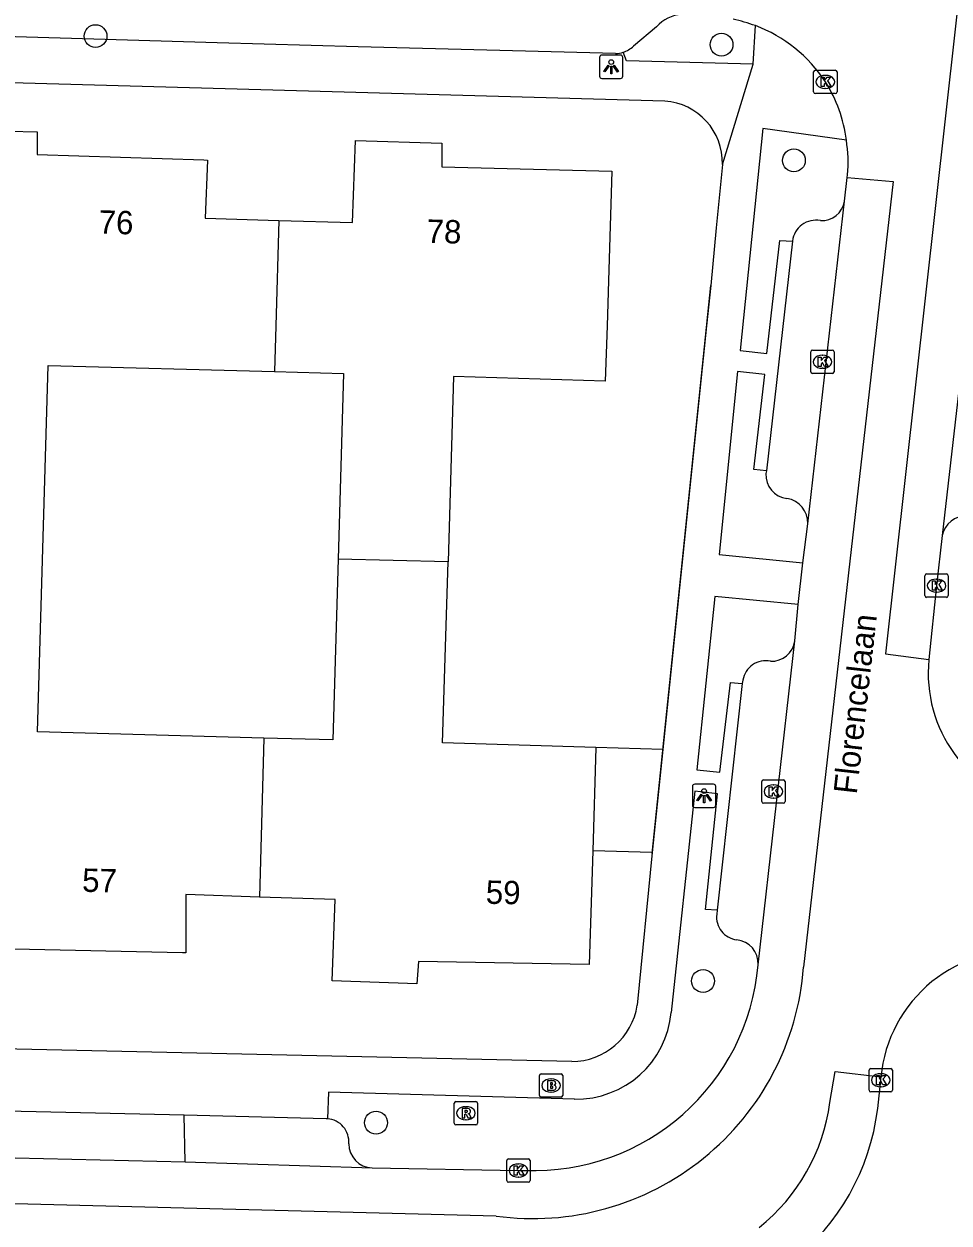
# Model space of a CAD drawing. Extents: x 162082 to 163393, y 388091 to 388632.
# Drawn here: x 162691.6 to 162731.2, y 388461.6 to 388512.9 of the extents above; entities that cross this region are included whole.
import ezdxf

# ---------------------------------------------------------------- set-up
doc = ezdxf.new("R2010")
doc.units = 0
for name, color, linetype in [('IMGEO_Boom', 7, 'Continuous'), ('IMGEO_Brandkraan', 7, 'Continuous'), ('IMGEO_Kolk', 7, 'Continuous'), ('IMGEO_Lichtpunt', 7, 'Continuous'), ('IMGEO_Muur', 7, 'Continuous'), ('IMGEO_Openbare_ruimte_label', 7, 'Continuous'), ('IMGEO_Pand', 7, 'Continuous'), ('IMGEO_Pand_nummerreeks', 7, 'Continuous'), ('IMGEO_Parkeervlak_open', 7, 'Continuous'), ('IMGEO_Rijbaan_lokaal_gesloten', 7, 'Continuous'), ('IMGEO_Rijbaan_lokaal_open', 7, 'Continuous'), ('IMGEO_Rioolput', 7, 'Continuous'), ('IMGEO_Voetpad_open', 7, 'Continuous')]:
    doc.layers.add(name, color=color, linetype=linetype)

msp = doc.modelspace()

# ---------------------------------------------------------------- linework, layer by layer
at = {"layer": 'IMGEO_Boom'}
for centre in [(162694.656, 388512.408), (162721.466, 388512.043), (162724.565, 388507.085), (162720.675, 388471.937), (162706.669, 388465.867)]:
    msp.add_circle(centre, 0.489, dxfattribs=at)
at = {"layer": 'IMGEO_Brandkraan'}
for p, q in [((162713.665, 388467.034), (162713.665, 388467.886)), ((162713.74, 388467.96), (162714.592, 388467.96)), ((162714.153, 388467.74), (162714.178, 388467.74)), ((162714.666, 388467.886), (162714.666, 388467.034)), ((162714.176, 388467.18), (162714.151, 388467.18)), ((162714.592, 388466.96), (162713.74, 388466.96))]:
    msp.add_line(p, q, dxfattribs=at)
for points in [[(162713.665, 388467.034), (162713.665, 388467.886)], [(162713.74, 388467.96), (162714.592, 388467.96)], [(162714.013, 388467.66), (162714.013, 388467.26), (162714.226, 388467.26)], [(162714.244, 388467.66), (162714.013, 388467.66)], [(162714.192, 388467.579), (162714.138, 388467.579), (162714.138, 388467.503)], [(162714.138, 388467.503), (162714.191, 388467.503)], [(162714.666, 388467.886), (162714.666, 388467.034)], [(162714.2, 388467.427), (162714.138, 388467.427), (162714.138, 388467.346)], [(162714.138, 388467.346), (162714.2, 388467.346)], [(162714.592, 388466.96), (162713.74, 388466.96)]]:
    msp.add_lwpolyline(points, dxfattribs=at)
for centre, radius, start, end in [((162713.742, 388467.884), 0.0765, 91.552, 178.448), ((162713.742, 388467.884), 0.0765, 91.552, 178.448), ((162714.193, 388467.541), 0.0379, 267.8285, 90.9355), ((162714.248, 388467.515), 0.145, 59.4692, 91.5367), ((162714.273, 388467.562), 0.0922, 285.5137, 58.1501), ((162714.59, 388467.884), 0.0765, 1.552, 88.448), ((162714.59, 388467.884), 0.0765, 1.552, 88.448), ((162713.742, 388467.036), 0.0765, 181.552, 268.448), ((162713.742, 388467.036), 0.0765, 181.552, 268.448), ((162714.201, 388467.386), 0.0404, 269.8759, 90.5077), ((162714.232, 388467.511), 0.251, 268.6676, 293.5347), ((162714.278, 388467.37), 0.105, 301.3115, 78.989), ((162714.59, 388467.036), 0.0765, 271.552, 358.448), ((162714.59, 388467.036), 0.0765, 271.552, 358.448)]:
    msp.add_arc(centre, radius, start, end, dxfattribs=at)
for centre, major_axis, ratio, start_param, end_param in [((162714.152, 388467.46), (-0.387, 0.002), 0.722429, 4.712389, 7.853982), ((162714.177, 388467.46), (-0.39, 0.002), 0.717154, 1.570796, 4.712389)]:
    msp.add_ellipse(centre, major_axis=major_axis, ratio=ratio, start_param=start_param, end_param=end_param, dxfattribs=at)
at = {"layer": 'IMGEO_Kolk'}
for p, q in [((162725.411, 388510.021), (162725.411, 388510.873)), ((162725.486, 388510.947), (162726.338, 388510.947)), ((162725.899, 388510.727), (162725.924, 388510.727)), ((162726.412, 388510.873), (162726.412, 388510.021)), ((162725.922, 388510.167), (162725.897, 388510.167)), ((162726.338, 388509.947), (162725.486, 388509.947)), ((162725.288, 388498.035), (162725.288, 388498.887)), ((162725.363, 388498.961), (162726.215, 388498.961)), ((162726.289, 388498.887), (162726.289, 388498.035)), ((162725.776, 388498.741), (162725.801, 388498.741)), ((162726.215, 388497.961), (162725.363, 388497.961)), ((162725.799, 388498.181), (162725.774, 388498.181)), ((162730.174, 388488.444), (162730.174, 388489.296)), ((162730.249, 388489.37), (162731.101, 388489.37)), ((162730.662, 388489.15), (162730.687, 388489.15)), ((162731.175, 388489.296), (162731.175, 388488.444)), ((162730.685, 388488.59), (162730.66, 388488.59)), ((162731.101, 388488.37), (162730.249, 388488.37)), ((162723.188, 388479.626), (162723.188, 388480.478)), ((162723.263, 388480.552), (162724.115, 388480.552)), ((162723.676, 388480.332), (162723.701, 388480.332)), ((162724.189, 388480.478), (162724.189, 388479.626)), ((162724.115, 388479.552), (162723.263, 388479.552)), ((162723.699, 388479.772), (162723.674, 388479.772)), ((162727.785, 388467.26), (162727.785, 388468.112)), ((162727.86, 388468.186), (162728.712, 388468.186)), ((162728.786, 388468.112), (162728.786, 388467.26)), ((162728.273, 388467.966), (162728.298, 388467.966)), ((162728.712, 388467.186), (162727.86, 388467.186)), ((162728.296, 388467.406), (162728.271, 388467.406)), ((162712.267, 388463.392), (162712.267, 388464.244)), ((162712.342, 388464.318), (162713.194, 388464.318)), ((162712.755, 388464.098), (162712.78, 388464.098)), ((162713.268, 388464.244), (162713.268, 388463.392)), ((162712.778, 388463.538), (162712.753, 388463.538)), ((162713.194, 388463.318), (162712.342, 388463.318))]:
    msp.add_line(p, q, dxfattribs=at)
for points in [[(162725.411, 388510.021), (162725.411, 388510.873)], [(162725.486, 388510.947), (162726.338, 388510.947)], [(162725.732, 388510.647), (162725.855, 388510.647), (162725.855, 388510.496), (162725.985, 388510.647), (162726.149, 388510.647), (162726.003, 388510.496), (162726.156, 388510.247), (162726.004, 388510.247), (162725.919, 388510.411), (162725.855, 388510.344), (162725.855, 388510.247), (162725.732, 388510.247), (162725.732, 388510.647)], [(162726.412, 388510.873), (162726.412, 388510.021)], [(162726.338, 388509.947), (162725.486, 388509.947)], [(162725.288, 388498.035), (162725.288, 388498.887)], [(162725.363, 388498.961), (162726.215, 388498.961)], [(162726.289, 388498.887), (162726.289, 388498.035)], [(162725.609, 388498.661), (162725.732, 388498.661), (162725.732, 388498.51), (162725.862, 388498.661), (162726.026, 388498.661), (162725.88, 388498.51), (162726.033, 388498.261), (162725.881, 388498.261), (162725.796, 388498.425), (162725.732, 388498.358), (162725.732, 388498.261), (162725.609, 388498.261), (162725.609, 388498.661)], [(162726.215, 388497.961), (162725.363, 388497.961)], [(162730.174, 388488.444), (162730.174, 388489.296)], [(162730.249, 388489.37), (162731.101, 388489.37)], [(162730.495, 388489.07), (162730.618, 388489.07), (162730.618, 388488.919), (162730.748, 388489.07), (162730.912, 388489.07), (162730.766, 388488.919), (162730.919, 388488.67), (162730.767, 388488.67), (162730.682, 388488.834), (162730.618, 388488.767), (162730.618, 388488.67), (162730.495, 388488.67), (162730.495, 388489.07)], [(162731.175, 388489.296), (162731.175, 388488.444)], [(162731.101, 388488.37), (162730.249, 388488.37)], [(162723.188, 388479.626), (162723.188, 388480.478)], [(162723.263, 388480.552), (162724.115, 388480.552)], [(162724.189, 388480.478), (162724.189, 388479.626)], [(162723.509, 388480.252), (162723.632, 388480.252), (162723.632, 388480.101), (162723.762, 388480.252), (162723.926, 388480.252), (162723.78, 388480.101), (162723.933, 388479.852), (162723.781, 388479.852), (162723.696, 388480.016), (162723.632, 388479.949), (162723.632, 388479.852), (162723.509, 388479.852), (162723.509, 388480.252)], [(162724.115, 388479.552), (162723.263, 388479.552)], [(162727.785, 388467.26), (162727.785, 388468.112)], [(162727.86, 388468.186), (162728.712, 388468.186)], [(162728.786, 388468.112), (162728.786, 388467.26)], [(162728.106, 388467.886), (162728.229, 388467.886), (162728.229, 388467.735), (162728.359, 388467.886), (162728.523, 388467.886), (162728.377, 388467.735), (162728.53, 388467.486), (162728.378, 388467.486), (162728.293, 388467.65), (162728.229, 388467.583), (162728.229, 388467.486), (162728.106, 388467.486), (162728.106, 388467.886)], [(162728.712, 388467.186), (162727.86, 388467.186)], [(162712.267, 388463.392), (162712.267, 388464.244)], [(162712.342, 388464.318), (162713.194, 388464.318)], [(162712.588, 388464.018), (162712.711, 388464.018), (162712.711, 388463.867), (162712.841, 388464.018), (162713.005, 388464.018), (162712.859, 388463.867), (162713.012, 388463.618), (162712.86, 388463.618), (162712.775, 388463.782), (162712.711, 388463.715), (162712.711, 388463.618), (162712.588, 388463.618), (162712.588, 388464.018)], [(162713.268, 388464.244), (162713.268, 388463.392)], [(162713.194, 388463.318), (162712.342, 388463.318)]]:
    msp.add_lwpolyline(points, dxfattribs=at)
for centre, start, end in [((162725.488, 388510.871), 91.552, 178.448), ((162725.488, 388510.871), 91.552, 178.448), ((162726.336, 388510.871), 1.552, 88.448), ((162726.336, 388510.871), 1.552, 88.448), ((162725.488, 388510.023), 181.552, 268.448), ((162725.488, 388510.023), 181.552, 268.448), ((162726.336, 388510.023), 271.552, 358.448), ((162726.336, 388510.023), 271.552, 358.448), ((162725.365, 388498.885), 91.552, 178.448), ((162725.365, 388498.885), 91.552, 178.448), ((162726.213, 388498.885), 1.552, 88.448), ((162726.213, 388498.885), 1.552, 88.448), ((162725.365, 388498.037), 181.552, 268.448), ((162725.365, 388498.037), 181.552, 268.448), ((162726.213, 388498.037), 271.552, 358.448), ((162726.213, 388498.037), 271.552, 358.448), ((162730.251, 388489.294), 91.552, 178.448), ((162730.251, 388489.294), 91.552, 178.448), ((162731.099, 388489.294), 1.552, 88.448), ((162731.099, 388489.294), 1.552, 88.448), ((162730.251, 388488.446), 181.552, 268.448), ((162730.251, 388488.446), 181.552, 268.448), ((162731.099, 388488.446), 271.552, 358.448), ((162731.099, 388488.446), 271.552, 358.448), ((162723.265, 388480.476), 91.552, 178.448), ((162723.265, 388480.476), 91.552, 178.448), ((162724.113, 388480.476), 1.552, 88.448), ((162724.113, 388480.476), 1.552, 88.448), ((162723.265, 388479.628), 181.552, 268.448), ((162723.265, 388479.628), 181.552, 268.448), ((162724.113, 388479.628), 271.552, 358.448), ((162724.113, 388479.628), 271.552, 358.448), ((162727.862, 388468.11), 91.552, 178.448), ((162727.862, 388468.11), 91.552, 178.448), ((162728.71, 388468.11), 1.552, 88.448), ((162728.71, 388468.11), 1.552, 88.448), ((162727.862, 388467.262), 181.552, 268.448), ((162727.862, 388467.262), 181.552, 268.448), ((162728.71, 388467.262), 271.552, 358.448), ((162728.71, 388467.262), 271.552, 358.448), ((162712.344, 388464.242), 91.552, 178.448), ((162712.344, 388464.242), 91.552, 178.448), ((162713.192, 388464.242), 1.552, 88.448), ((162713.192, 388464.242), 1.552, 88.448), ((162712.344, 388463.394), 181.552, 268.448), ((162712.344, 388463.394), 181.552, 268.448), ((162713.192, 388463.394), 271.552, 358.448), ((162713.192, 388463.394), 271.552, 358.448)]:
    msp.add_arc(centre, 0.0765, start, end, dxfattribs=at)
for centre, major_axis, ratio, start_param, end_param in [((162725.898, 388510.447), (-0.387, 0.002), 0.722429, 4.712389, 7.853982), ((162725.923, 388510.447), (-0.39, 0.002), 0.717154, 1.570796, 4.712389), ((162725.775, 388498.461), (-0.387, 0.002), 0.722429, 4.712389, 7.853982), ((162725.8, 388498.461), (-0.39, 0.002), 0.717154, 1.570796, 4.712389), ((162730.661, 388488.87), (-0.387, 0.002), 0.722429, 4.712389, 7.853982), ((162730.686, 388488.87), (-0.39, 0.002), 0.717154, 1.570796, 4.712389), ((162723.675, 388480.052), (-0.387, 0.002), 0.722429, 4.712389, 7.853982), ((162723.7, 388480.052), (-0.39, 0.002), 0.717154, 1.570796, 4.712389), ((162728.272, 388467.686), (-0.387, 0.002), 0.722429, 4.712389, 7.853982), ((162728.297, 388467.686), (-0.39, 0.002), 0.717154, 1.570796, 4.712389), ((162712.754, 388463.818), (-0.387, 0.002), 0.722429, 4.712389, 7.853982), ((162712.779, 388463.818), (-0.39, 0.002), 0.717154, 1.570796, 4.712389)]:
    msp.add_ellipse(centre, major_axis=major_axis, ratio=ratio, start_param=start_param, end_param=end_param, dxfattribs=at)
at = {"layer": 'IMGEO_Lichtpunt'}
for p, q in [((162716.242, 388511.498), (162716.242, 388510.691)), ((162716.242, 388511.498), (162716.242, 388510.691)), ((162717.144, 388511.593), (162716.336, 388511.593)), ((162717.144, 388511.593), (162716.336, 388511.593)), ((162717.238, 388510.691), (162717.238, 388511.498)), ((162717.238, 388510.691), (162717.238, 388511.498)), ((162716.336, 388510.597), (162717.144, 388510.597)), ((162716.336, 388510.597), (162717.144, 388510.597)), ((162721.124, 388480.367), (162720.316, 388480.367)), ((162721.124, 388480.367), (162720.316, 388480.367)), ((162720.222, 388480.272), (162720.222, 388479.465)), ((162720.222, 388480.272), (162720.222, 388479.465)), ((162721.218, 388479.465), (162721.218, 388480.272)), ((162721.218, 388479.465), (162721.218, 388480.272)), ((162720.316, 388479.371), (162721.124, 388479.371)), ((162720.316, 388479.371), (162721.124, 388479.371))]:
    msp.add_line(p, q, dxfattribs=at)
for points in [[(162716.616, 388511.162), (162716.655, 388511.134), (162716.467, 388510.872), (162716.429, 388510.899), (162716.616, 388511.162)], [(162716.828, 388511.134), (162716.866, 388511.161), (162717.053, 388510.899), (162717.014, 388510.871), (162716.828, 388511.134)], [(162716.718, 388511.114), (162716.765, 388511.114), (162716.765, 388510.792), (162716.718, 388510.792), (162716.718, 388511.114)], [(162720.596, 388479.936), (162720.635, 388479.908), (162720.447, 388479.646), (162720.409, 388479.673), (162720.596, 388479.936)], [(162720.698, 388479.888), (162720.745, 388479.888), (162720.745, 388479.566), (162720.698, 388479.566), (162720.698, 388479.888)], [(162720.808, 388479.908), (162720.846, 388479.935), (162721.033, 388479.673), (162720.994, 388479.645), (162720.808, 388479.908)]]:
    msp.add_lwpolyline(points, dxfattribs=at)
for centre in [(162716.741, 388511.296), (162720.721, 388480.07)]:
    msp.add_circle(centre, 0.0994, dxfattribs=at)
for centre, start, end in [((162716.336, 388511.498), 90, 180), ((162716.336, 388511.498), 90, 180), ((162717.144, 388511.498), 0, 90), ((162717.144, 388511.498), 0, 90), ((162716.336, 388510.691), 180, 270), ((162716.336, 388510.691), 180, 270), ((162717.144, 388510.691), 270, 0), ((162717.144, 388510.691), 270, 360), ((162720.316, 388480.272), 90, 180), ((162720.316, 388480.272), 90, 180), ((162721.124, 388480.272), 0, 90), ((162721.124, 388480.272), 0, 90), ((162720.316, 388479.465), 180, 270), ((162720.316, 388479.465), 180, 270), ((162721.124, 388479.465), 270, 0), ((162721.124, 388479.465), 270, 360)]:
    msp.add_arc(centre, 0.0946, start, end, dxfattribs=at)
at = {"layer": 'IMGEO_Muur'}
msp.add_lwpolyline([(162718.494, 388477.4), (162721.005, 388501.733)], dxfattribs=at)
at = {"layer": 'IMGEO_Pand'}
for points in [[(162688.376, 388504.925), (162688.498, 388508.4), (162692.16, 388508.303), (162692.163, 388507.343), (162699.297, 388507.106), (162699.452, 388507.101), (162699.352, 388504.607), (162702.511, 388504.517)], [(162702.511, 388504.517), (162705.662, 388504.428), (162705.793, 388507.94), (162709.493, 388507.816), (162709.484, 388506.815), (162716.762, 388506.62), (162716.619, 388501.92), (162716.561, 388500), (162716.489, 388497.633), (162709.993, 388497.831), (162709.752, 388489.889)], [(162702.511, 388504.517), (162702.374, 388500), (162702.315, 388498.038)], [(162701.868, 388482.343), (162692.167, 388482.605), (162692.624, 388498.3), (162702.315, 388498.038)], [(162702.315, 388498.038), (162705.28, 388497.958), (162705.049, 388490.008)], [(162705.049, 388490.008), (162704.823, 388482.263), (162701.868, 388482.343)], [(162709.752, 388489.889), (162705.049, 388490.008)], [(162716.086, 388481.937), (162709.516, 388482.137), (162709.752, 388489.889)], [(162701.868, 388482.343), (162701.679, 388475.533)], [(162716.086, 388481.937), (162715.952, 388477.517)], [(162718.953, 388481.85), (162716.086, 388481.937)], [(162718.953, 388481.85), (162718.498, 388477.44)], [(162715.952, 388477.517), (162715.804, 388472.643), (162708.484, 388472.778), (162708.421, 388471.816), (162704.797, 388471.945), (162704.917, 388475.425), (162701.679, 388475.533)], [(162718.498, 388477.44), (162715.952, 388477.517)], [(162701.679, 388475.533), (162698.522, 388475.638), (162698.521, 388473.143), (162698.385, 388473.146), (162691.172, 388473.301), (162691.167, 388472.332), (162687.472, 388472.435), (162687.56, 388475.928)]]:
    msp.add_lwpolyline(points, dxfattribs=at)
at = {"layer": 'IMGEO_Parkeervlak_open'}
for points in [[(162718.687, 388512.806), (162717.694, 388511.979)], [(162723.394, 388493.794), (162723.37, 388493.671)], [(162722.384, 388484.824), (162722.351, 388484.679)], [(162721.275, 388474.976), (162721.262, 388474.793)], [(162698.496, 388464.193), (162698.457, 388466.189)]]:
    msp.add_lwpolyline(points, dxfattribs=at)
for centre, radius, start, end in [((162719.886, 388511.747), 1.6, 94.4179, 138.5417), ((162716.885, 388512.842), 1.183, 288.187, 313.1643), ((162725.764, 388505.481), 0.978, 266.2082, 351.5434), ((162725.507, 388503.514), 1.01, 79.046, 173.4409), ((162724.378, 388493.608), 1.01, 176.4126, 263.8189), ((162724.089, 388491.547), 1.072, 358.4011, 80.344), ((162731.93, 388490.828), 1.026, 87.2786, 169.4036), ((162723.609, 388486.635), 1.003, 267.2512, 352.7371), ((162723.354, 388484.674), 0.982, 77.8228, 171.1819), ((162722.226, 388474.669), 0.971, 172.6897, 263.5829), ((162722.01, 388472.686), 1.023, 357.069, 84.0012), ((162704.517, 388465.049), 0.988, 355.2024, 85.7257), ((162706.54, 388464.968), 1.038, 180.1014, 267.641)]:
    msp.add_arc(centre, radius, start, end, dxfattribs=at)
at = {"layer": 'IMGEO_Rijbaan_lokaal_gesloten'}
for points in [[(162738.143, 388554.92), (162736.204, 388555.092), (162728.485, 388485.946), (162730.347, 388485.702)], [(162726.846, 388506.359), (162728.813, 388506.183), (162724.977, 388472.525)], [(162726.731, 388505.337), (162726.846, 388506.359)], [(162725.161, 388491.517), (162726.731, 388505.337)], [(162732.479, 388504.706), (162730.922, 388491.017)], [(162724.955, 388489.853), (162725.161, 388491.517)], [(162730.922, 388491.017), (162730.675, 388488.87), (162730.347, 388485.702)], [(162724.755, 388488.061), (162724.955, 388489.853)], [(162724.604, 388486.508), (162724.755, 388488.061)], [(162723.032, 388472.634), (162724.604, 388486.508)], [(162726.111, 388466.73), (162726.336, 388468.06), (162728.294, 388467.825)], [(162728.155, 388466.47), (162728.286, 388467.686), (162728.294, 388467.825)], [(162687.566, 388464.449), (162698.496, 388464.193)], [(162711.816, 388461.865), (162675.589, 388462.798), (162618.463, 388464.27)], [(162698.496, 388464.193), (162706.497, 388463.931)], [(162706.497, 388463.931), (162712.768, 388463.818), (162713.048, 388463.823)]]:
    msp.add_lwpolyline(points, dxfattribs=at)
for centre, radius, start, end in [((162713.444, 388473.436), 9.621, 267.641, 355.2166), ((162713.38, 388473.388), 11.629, 262.2681, 355.7447), ((162718.317, 388467.688), 9.913, 264.4488, 352.9446), ((162717.927, 388467.835), 8.258, 308.5902, 352.3106)]:
    msp.add_arc(centre, radius, start, end, dxfattribs=at)
at = {"layer": 'IMGEO_Rijbaan_lokaal_open'}
msp.add_lwpolyline([(162726.846, 388506.359), (162726.859, 388506.471)], dxfattribs=at)
for centre, radius, start, end in [((162719.98, 388504.601), 8.762, 70.4338, 76.9304), ((162720.751, 388507.097), 6.153, 32.9899, 69.4206), ((162720.869, 388507.217), 5.989, 7.0901, 32.6396), ((162721.365, 388507.04), 5.523, 354.0832, 9.5424), ((162736.161, 388485.113), 5.844, 174.22, 257.8164), ((162734.242, 388467.27), 5.974, 83.4797, 174.6702)]:
    msp.add_arc(centre, radius, start, end, dxfattribs=at)
at = {"layer": 'IMGEO_Rioolput'}
for p, q in [((162710.018, 388465.847), (162710.018, 388466.699)), ((162710.093, 388466.773), (162710.945, 388466.773)), ((162710.506, 388466.553), (162710.531, 388466.553)), ((162711.019, 388466.699), (162711.019, 388465.847)), ((162710.529, 388465.993), (162710.504, 388465.993)), ((162710.945, 388465.773), (162710.093, 388465.773))]:
    msp.add_line(p, q, dxfattribs=at)
for points in [[(162710.018, 388465.847), (162710.018, 388466.699)], [(162710.093, 388466.773), (162710.945, 388466.773)], [(162710.607, 388466.471), (162710.355, 388466.473), (162710.355, 388466.073)], [(162711.019, 388466.699), (162711.019, 388465.847)], [(162710.355, 388466.073), (162710.479, 388466.073), (162710.479, 388466.235), (162710.49, 388466.235)], [(162710.533, 388466.392), (162710.479, 388466.392), (162710.479, 388466.311)], [(162710.479, 388466.311), (162710.531, 388466.311)], [(162710.537, 388466.206), (162710.608, 388466.073), (162710.748, 388466.073), (162710.683, 388466.199)], [(162710.945, 388465.773), (162710.093, 388465.773)]]:
    msp.add_lwpolyline(points, dxfattribs=at)
for centre, radius, start, end in [((162710.095, 388466.697), 0.0765, 91.552, 178.448), ((162710.095, 388466.697), 0.0765, 91.552, 178.448), ((162710.606, 388466.361), 0.109, 350.3612, 89.416), ((162710.943, 388466.697), 0.0765, 1.552, 88.448), ((162710.943, 388466.697), 0.0765, 1.552, 88.448), ((162710.489, 388466.182), 0.0533, 26.0293, 88.6989), ((162710.515, 388466.5), 0.19, 274.7715, 282.9687), ((162710.539, 388466.296), 0.0964, 77.0061, 93.1865), ((162710.553, 388466.353), 0.0378, 276.6634, 79.6772), ((162710.604, 388466.361), 0.112, 277.5842, 350.9817), ((162710.588, 388466.146), 0.108, 29.5134, 73.7905), ((162710.095, 388465.849), 0.0765, 181.552, 268.448), ((162710.095, 388465.849), 0.0765, 181.552, 268.448), ((162710.943, 388465.849), 0.0765, 271.552, 358.448), ((162710.943, 388465.849), 0.0765, 271.552, 358.448)]:
    msp.add_arc(centre, radius, start, end, dxfattribs=at)
for centre, major_axis, ratio, start_param, end_param in [((162710.505, 388466.273), (-0.387, 0.002), 0.722429, 4.712389, 7.853982), ((162710.53, 388466.273), (-0.39, 0.002), 0.717154, 1.570796, 4.712389)]:
    msp.add_ellipse(centre, major_axis=major_axis, ratio=ratio, start_param=start_param, end_param=end_param, dxfattribs=at)
at = {"layer": 'IMGEO_Voetpad_open'}
for points in [[(162716.929, 388511.658), (162705.906, 388511.956), (162699.863, 388512.119), (162689.291, 388512.438), (162685.537, 388512.524), (162679.564, 388512.699)], [(162722.826, 388511.207), (162722.914, 388512.857)], [(162722.826, 388511.207), (162717.399, 388511.356), (162717.254, 388511.718)], [(162721.505, 388506.911), (162722.826, 388511.207)], [(162665.584, 388511.139), (162719.033, 388509.629)], [(162726.812, 388507.956), (162723.233, 388508.447), (162722.262, 388498.946), (162723.407, 388498.816), (162723.956, 388503.653), (162724.504, 388503.629)], [(162721.505, 388506.911), (162721.231, 388504.19), (162721.005, 388501.733), (162720.826, 388500), (162718.953, 388481.85)], [(162724.504, 388503.629), (162723.394, 388493.794)], [(162723.394, 388493.794), (162722.844, 388493.839), (162723.315, 388497.908), (162722.156, 388498.046), (162721.36, 388490.207), (162724.955, 388489.853)], [(162724.755, 388488.061), (162721.177, 388488.408), (162720.409, 388480.977), (162721.391, 388480.881), (162721.845, 388484.72), (162722.351, 388484.679)], [(162722.351, 388484.679), (162721.275, 388474.976)], [(162721.275, 388474.976), (162720.783, 388475.005), (162721.3, 388479.952), (162720.329, 388480.074), (162719.306, 388470.592)], [(162718.498, 388477.44), (162717.859, 388470.902)], [(162715.058, 388468.484), (162684.212, 388469.173), (162668.046, 388469.711), (162618.648, 388471.136)], [(162715.162, 388466.88), (162704.633, 388467.177), (162704.591, 388466.034)], [(162698.457, 388466.189), (162687.661, 388466.43)], [(162704.591, 388466.034), (162704.563, 388466.036), (162704.535, 388466.037), (162698.457, 388466.189)]]:
    msp.add_lwpolyline(points, dxfattribs=at)
for centre, radius, start, end in [((162716.873, 388512.874), 1.217, 272.6559, 288.2639), ((162718.848, 388506.977), 2.658, 358.5699, 86.0026), ((162715.037, 388471.34), 2.856, 270.4261, 351.1795), ((162715.253, 388470.947), 4.068, 268.7115, 354.9935)]:
    msp.add_arc(centre, radius, start, end, dxfattribs=at)

# ---------------------------------------------------------------- texts
at = {"layer": 'IMGEO_Openbare_ruimte_label'}
msp.add_text('Florencelaan', height=1, rotation=83.5713, dxfattribs=at).set_placement((162727.255, 388479.909))
at = {"layer": 'IMGEO_Pand_nummerreeks'}
for s, rotation, p in [('76', 358.3981, (162694.78, 388503.953)), ('78', 358.3981, (162708.826, 388503.56)), ('57', 358.7684, (162694.075, 388475.759)), ('59', 358.9458, (162711.364, 388475.245))]:
    msp.add_text(s, height=1, rotation=rotation, dxfattribs=at).set_placement(p)

doc.saveas('drawing.dxf')
